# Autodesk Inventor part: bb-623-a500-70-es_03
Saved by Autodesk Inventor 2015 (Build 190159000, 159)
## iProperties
Created: 2022-04
Part Number: bb-623-a500-70-es_03
Checked By: TraceParts S.A.
Material: Generic
Catalog Web Link: www.traceparts.com
Document SubType Name: Modeling
Designer: TraceParts
Density: 1 g/cm^3
Appearance: Default
Company: TraceParts S.A.
Author: TraceParts
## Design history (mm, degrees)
feature "bb-623-a500-70-es_03.ipt"
body "Solid1"
